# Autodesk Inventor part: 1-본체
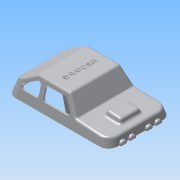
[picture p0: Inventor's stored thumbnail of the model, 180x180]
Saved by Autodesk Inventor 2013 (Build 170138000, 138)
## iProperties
Created: 2015-05
Part Number: 1-본체
Material: ABS 플라스틱
Document SubType Name: Modeling
Designer: Administrator
Density: 1.06 g/cm^3
Mass: 36.8459 g
Surface Area: 320.288 cm^2
Volume: 34.7603 cm^3
Author: Administrator
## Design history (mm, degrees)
sketch "스케치1"
  geometry: L1 (-61, 38)-(61, 38); L2 (61, 38)-(61, -38); L3 (61, -38)-(-61, -38); L4 (-61, -38)-(-61, 38); L5 (-61, 38)-(61, -38); L6 (61, 38)-(-61, -38); 1 further point
  constraints: 12 end point, 2 midpoint, 2 parallel, 1 horizontal, 1 perpendicular
  dimensions: "d0" = 122 distance of L2.end L3.end; "d2" = 76 distance of L1.end L2.end
extrude "돌출1" new body sketch "스케치1" distance "d3" = 30; taper "d4" = -15 deg
sketch "스케치2"
  geometry: L1 (52.962, 30)-(-52.962, 30) reference; L2 (-61, 0)-(-52.962, 30) reference; L3 (61, 0)-(52.962, 30) reference; L4 (-7.174, 30)-(-19, 11.075); L5 (-19, 11.075)-(-58.588, 9); L6 (61, 0)-(-61, 0) reference; L7 (61, 0)-(61, 28.689); L8 (31, 30)-(61, 11.254); L9 (57.378, 13.517)-(52.962, 30); 2 further points
  constraints: 10 end point, 6 point on line, 2 perpendicular, 1 coincident, 1 collinear
  dimensions: "d7" = 125 deg angle of L4 L5; "d10" = 42 horizontal distance of point (-61, 0) L4.end; "d11" = 9 vertical distance of point (-61, 0) L5.end; "d12" = 3 deg angle of L6 L5; "d13" = 30 horizontal distance of L8.start L8.end
extrude "돌출2" cut sketch "스케치2" stored distance "d14" = 30; taper "d15" = 0 deg
sketch "스케치3"
  geometry: L1 (-28.121, 48.588)-(-8.121, 48.588); L2 (-8.121, 48.588)-(-8.121, 22.588); L3 (-8.121, 22.588)-(-28.121, 22.588); L4 (-28.121, 22.588)-(-28.121, 48.588); L5 (-28.121, 48.588)-(-8.121, 22.588); L6 (-8.121, 48.588)-(-28.121, 22.588); L7 (2.879, 73.588)-(2.879, -2.412) reference; 3 further points
  constraints: 12 end point, 3 midpoint, 2 parallel, 1 horizontal, 1 horizontal alignment, 1 perpendicular
  dimensions: "d16" = 20 distance of L1.start L1.end; "d18" = 11 distance between parallel lines of L7 L2; "d19" = 26 distance of L1.end L2.end
extrude "돌출3" join sketch "스케치3" distance "d20" = 5; taper "d21" = -20 deg
fillet "모깎기4" dims "d95" = 3, "d104" = 12
fillet "모깎기7" dims "d105" = 3
feature "쉘1" dims "d30" = 2
sketch "스케치4"
  geometry: L1 (-5.284, 23.59)-(-10.908, 14.59); L2 (-8.364, 10)-(17.224, 10); L3 (20.224, 13)-(20.224, 22); L4 (17.224, 25)-(-2.74, 25); L5 (31, 30)-(-7.174, 30) reference; L6 (57.378, 13.517)-(31, 30) reference; L7 (-7.174, 30)-(-19, 11.075) reference; L8 (28.571, 10)-(43.109, 10); L9 (25.571, 13)-(25.571, 21.896); L10 (44.699, 15.544)-(30.321, 24.528); A1 r 3 centre (-2.74, 22) between (-2.74, 25) and (-5.284, 23.59); A2 r 3 centre (-8.364, 13) between (-10.908, 14.59) and (-8.364, 10); A3 r 3 centre (17.224, 13) between (17.224, 10) and (20.224, 13); A4 r 3 centre (28.571, 13) between (25.571, 13) and (28.571, 10); A5 r 3 centre (43.109, 13) between (43.109, 10) and (44.699, 15.544); A6 r 3 centre (17.224, 22) between (20.224, 22) and (17.224, 25); A7 r 3.104 centre (28.676, 21.896) between (30.321, 24.528) and (25.571, 21.896); 6 further points
  constraints: 14 end point, 14 point on circle, 14 tangent, 10 point on line, 7 centre point, 5 equal radius, 3 parallel, 3 perpendicular, 1 collinear, 1 horizontal
  dimensions: "d23" = 5 distance between parallel lines of L5 L4; "d24" = 5 distance between parallel lines of L7 L1; "d25" = 15 distance of point (20.224, 10) point (20.224, 25); "d26" = 34 distance of point (-13.776, 10) point (20.224, 10); "d29" = 28 distance of point (25.571, 10) point (53.571, 10); "d32" = 5 distance between parallel lines of L6 L10; "d34" = 3 radius of A1; "d35" = 3.1045 radius of A7
extrude "돌출4" cut sketch "스케치4" stored distance "d36" = 5; taper "d37" = 0 deg
node "작업 평면1"
sketch "스케치5"
  geometry: A1 r 4 centre (-10, 0) between (-6, 0) and (-14, 0); A2 r 4 centre (-21, 0) between (-17, 0) and (-25, 0); A3 r 4 centre (10, 0) between (14, 0) and (6, 0); A4 r 4 centre (21, 0) between (25, 0) and (17, 0); 7 further points
  constraints: 8 point on circle, 4 centre point, 3 equal radius, 13 other
  dimensions: "d39" = 4 radius of A4; "d41" = 20 distance of A3.centre A1.centre; "d42" = 11 distance of A4.centre A3.centre; "d43" = 11 distance of A1.centre A2.centre; "d44" = 10 distance of point (0, 0) A1.centre
extrude "돌출5" join sketch "스케치5" stored distance "d45" = 5; taper "d46" = 0 deg
sketch "스케치6"
  geometry: L1 (5, -21)-(-5, -21); L2 (-5, -21)-(-5, -23); L3 (-5, -23)-(5, -23); L4 (5, -23)-(5, -21); L5 (5, -21)-(-5, -23); L6 (-5, -21)-(5, -23); L7 (45, 1)-(35, 1); L8 (35, 1)-(35, -1); L9 (35, -1)-(45, -1); L10 (45, -1)-(45, 1); L11 (45, 1)-(35, -1); L12 (35, 1)-(45, -1); L13 (5, 23)-(-5, 23); L14 (-5, 23)-(-5, 21); L15 (-5, 21)-(5, 21); L16 (5, 21)-(5, 23); L17 (5, 23)-(-5, 21); L18 (-5, 23)-(5, 21); L19 (-35, 1)-(-45, 1); L20 (-45, 1)-(-45, -1); L21 (-45, -1)-(-35, -1); L22 (-35, -1)-(-35, 1); L23 (-35, 1)-(-45, -1); L24 (-45, 1)-(-35, -1); L25 (-61, -26.409)-(-61, 26.409) reference; L26 (49.409, -38)-(-49.409, -38) reference; 19 further points
  constraints: 48 end point, 15 midpoint, 8 parallel, 6 equal length, 4 horizontal, 4 perpendicular, 3 vertical alignment, 2 horizontal alignment
  dimensions: "d47" = 10 distance between parallel lines of L2 L4; "d49" = 2 distance of L3.end L1.start; "d50" = 44 distance of point (0, 22) point (0, -22); "d51" = 80 distance of point (-40, 0) point (40, 0); "d52" = 21 distance from line of L25 point (-40, 0); "d53" = 16 distance from line of L26 point (0, -22)
extrude "돌출6" join sketch "스케치6" stored distance "d54" = 5; taper "d55" = 0 deg
feature "면 기울기5" dims angle "d60" = 10 deg
feature "면 기울기6" dims angle "d61" = 10 deg
feature "면 기울기7" dims angle "d62" = 10 deg
feature "면 기울기8" dims angle "d63" = 10 deg
feature "면 기울기9" dims angle "d64" = 2.5 deg
feature "면 기울기10" dims angle "d65" = 2.5 deg
feature "면 기울기11" dims angle "d66" = 2.5 deg
feature "면 기울기12" dims angle "d67" = 2.5 deg
sketch "스케치7"
  geometry: L1 (-49.409, -38)-(49.409, -38) reference; C1 r 3 at (-40, 0); C2 r 3 at (0, -22); C3 r 3 at (40, 0); C4 r 3 at (0, 22); 5 further points
  constraints: 4 centre point, 3 equal radius, 2 horizontal alignment, 2 vertical alignment
  dimensions: "d68" = 6 diameter of C4; "d70" = 44 distance of C2.centre C4.centre; "d71" = 80 distance of C3.centre C1.centre; "d72" = 16 distance from line of L1 C2.centre; "d73" = 40 distance of point (0, 0) C1.centre
extrude "돌출7" join sketch "스케치7" stored distance "d74" = 5; taper "d75" = 2 deg
sketch "스케치8"
  geometry: L1 (-35, -1)-(-37.172, -1) reference; L2 (-35, 1)-(-35, -1) reference; L3 (-37.172, 1)-(-35, 1) reference; L4 (-45, 1)-(-42.828, 1) reference; L5 (-45, -1)-(-45, 1) reference; L6 (-42.828, -1)-(-45, -1) reference; L7 (-5, -21)-(-2.828, -21) reference; L8 (-5, -23)-(-5, -21) reference; L9 (-2.828, -23)-(-5, -23) reference; L10 (5, -23)-(2.828, -23) reference; L11 (5, -21)-(5, -23) reference; L12 (2.828, -21)-(5, -21) reference; L13 (35, 1)-(37.172, 1) reference; L14 (35, -1)-(35, 1) reference; L15 (37.172, -1)-(35, -1) reference; L16 (45, -1)-(42.828, -1) reference; L17 (45, 1)-(45, -1) reference; L18 (42.828, 1)-(45, 1) reference; A1 r 3 centre (0, 22) between (2.828, 23) and (-2.828, 23) reference; A2 r 3 centre (-40, 0) between (-37.172, 1) and (-42.828, 1) reference; A3 r 3 centre (-40, 0) between (-42.828, -1) and (-37.172, -1) reference; A4 r 3 centre (0, -22) between (-2.828, -23) and (2.828, -23) reference; A5 r 3 centre (0, -22) between (2.828, -21) and (-2.828, -21) reference; A6 r 3 centre (40, 0) between (37.172, -1) and (42.828, -1) reference; A7 r 3 centre (40, 0) between (42.828, 1) and (37.172, 1) reference; 5 further points
  constraints: 4 coincident
hole "구멍1" sketch "스케치8" at (-40, 0), (0, 22), (40, 0), (0, -22) diameter "d76" = 3.242; stored, may be unused: countersink angle "d80" = 90 deg, drill point angle "d82" = 118 deg; dims "d77" = 9, "d78" = 4, "d79" = 2, "d81" = 11
sketch "스케치9"
  geometry: L1 (31, 30)-(-7.174, 30) reference; L2 (-7.174, 30)-(-19, 11.075) reference; L3 (-19, 11.075)-(-19, 35.057); L4 (-19, 35.057)-(31, 35.057); L5 (31, 35.057)-(31, 30); L6 (-30.506, 10.472)-(-32.585, 15.37) reference; L7 (-32.585, 15.37)-(-19, 15.37); L8 (-30.506, 10.472)-(-19, 15.37); 1 further point
  constraints: 10 end point, 3 perpendicular, 1 parallel, 1 point on line
  dimensions: "d83" = 5.05695 distance between parallel lines of L1 L4
extrude "돌출8" cut sketch "스케치9" stored distance "d84" = 5; taper "d85" = 0 deg
sketch "스케치11"
  geometry: L1 (-61, -26.409)-(-61, 26.409) reference; 6 further points
  constraints: 1 horizontal alignment, 1 other
  dimensions: "d89" = 50 distance from line of L1 point (-11, 0)
feature "엠보싱1" sketch "스케치11" dims "d0" = 122, "d2" = 76, "d90" = 0.5, "d91" = 0
fillet "모깎기6" dims "d100" = 3
chamfer "모따기1" distance "d101" = 1; stored, may be unused: second distance "d102" = 2, angle "d103" = 45 deg
sketch "스케치13"
  geometry: L1 (58.929, 26.27)-(58.929, -26.27) reference; L2 (49.27, -35.929)-(-49.27, -35.929) reference; L3 (-58.929, -26.27)-(-58.929, 26.27) reference; L4 (-49.27, 35.929)-(49.27, 35.929) reference; L5 (49.27, 36.929)-(-49.27, 36.929); L6 (-59.929, 26.27)-(-59.929, -26.27); L7 (-49.27, -36.929)-(49.27, -36.929); L8 (59.929, -26.27)-(59.929, 26.27); 5 further points; 4 other entities
  constraints: 8 end point, 7 parallel, 16 other
  dimensions: "d106" = 1 distance between parallel lines of L8 L1
extrude "돌출11" join sketch "스케치13" distance "d107" = 1; taper "d108" = 0 deg
node "솔리드1"
node "투영된 루프1"
node "투영된 루프2"
node "투영된 루프3"
other parameters: "d38" = 63
